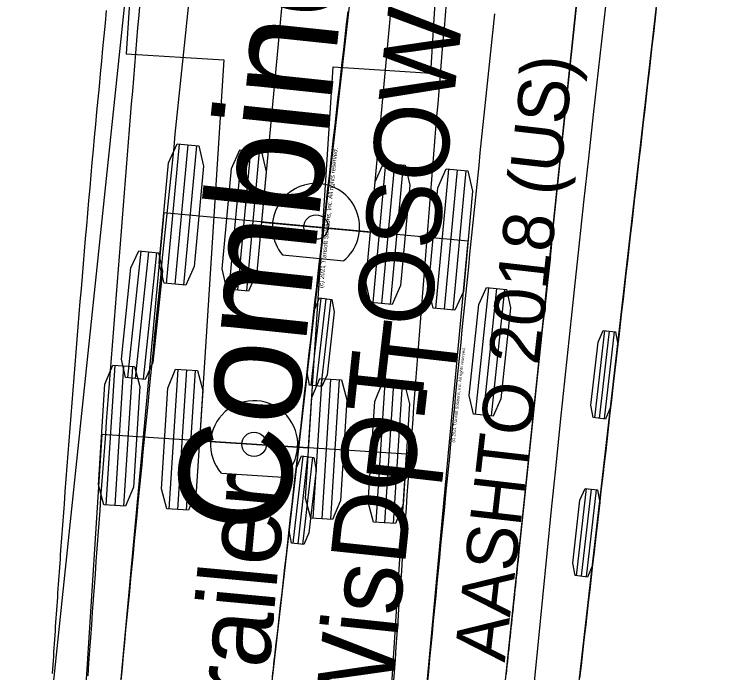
# Model space of a CAD drawing. Extents: x -14 to 1565148, y -25 to 642856.
# Drawn here: x 1564790.38 to 1564808.78, y 636112.11 to 636129.38 of the extents above; entities that cross this region are included whole.
import ezdxf

# ---------------------------------------------------------------- set-up
doc = ezdxf.new("R2010")
doc.units = 0
for name, color, linetype in [('DR_P_Drainage_Area', 7, 'Continuous'), ('GE_P_Alignment', 7, 'Continuous'), ('MT_P_Cells', 7, 'Continuous'), ('PF_P_Grade_Line', 7, 'Continuous'), ('PV_P_Curb', 7, 'Continuous'), ('PV_X_EOP', 7, 'Continuous')]:
    doc.layers.add(name, color=color, linetype=linetype)

msp = doc.modelspace()

# ---------------------------------------------------------------- linework, layer by layer
at = {"layer": 'DR_P_Drainage_Area'}
msp.add_arc((1566787.273, 635986.808), 1980, 175.493678, 179.898828, dxfattribs=at)
at = {"layer": 'GE_P_Alignment'}
msp.add_arc((1565898.839, 636005.315), 1092, 172.336069, 179.46316, dxfattribs=at)
at = {"layer": 'MT_P_Cells'}
for p, q in [((1564793.799, 636135.822), (1564793.32, 636128.337)), ((1564801.304, 636127.827), (1564801.783, 636135.312)), ((1564793.32, 636128.337), (1564795.882, 636128.174)), ((1564795.882, 636128.174), (1564795.244, 636118.194)), ((1564798.104, 636118.011), (1564798.743, 636127.991)), ((1564798.743, 636127.991), (1564801.304, 636127.827)), ((1564793.028, 636120.173), (1564792.794, 636116.514)), ((1564793.256, 636120.158), (1564793.022, 636116.499)), ((1564793.485, 636120.143), (1564793.251, 636116.484)), ((1564794.674, 636120.067), (1564794.44, 636116.408)), ((1564794.903, 636120.053), (1564794.669, 636116.394)), ((1564795.132, 636120.038), (1564794.898, 636116.379)), ((1564798.45, 636119.826), (1564798.216, 636116.167)), ((1564798.679, 636119.811), (1564798.445, 636116.152)), ((1564798.907, 636119.797), (1564798.673, 636116.138)), ((1564800.097, 636119.721), (1564799.863, 636116.061)), ((1564800.325, 636119.706), (1564800.091, 636116.047)), ((1564800.554, 636119.691), (1564800.32, 636116.032)), ((1564792.682, 636118.358), (1564790.385, 636082.431)), ((1564800.666, 636117.847), (1564792.682, 636118.358)), ((1564792.682, 636118.358), (1564792.682, 636118.358)), ((1564795.244, 636118.194), (1564798.104, 636118.011)), ((1564798.368, 636081.921), (1564800.666, 636117.847)), ((1564795.816, 636117.348), (1564797.429, 636117.244))]:
    msp.add_line(p, q, dxfattribs=at)
for points in [[(1564792.325, 636112.039), (1564792.348, 636112.372), (1564792.372, 636112.705), (1564792.396, 636113.038), (1564792.419, 636113.371), (1564792.443, 636113.703), (1564792.467, 636114.036), (1564792.491, 636114.369), (1564792.515, 636114.702), (1564792.54, 636115.035), (1564792.564, 636115.368), (1564792.588, 636115.701), (1564792.613, 636116.034), (1564792.637, 636116.367), (1564792.662, 636116.7), (1564792.686, 636117.033), (1564792.711, 636117.366), (1564792.736, 636117.699), (1564792.761, 636118.032), (1564792.786, 636118.365), (1564792.811, 636118.697), (1564792.836, 636119.03), (1564792.861, 636119.363), (1564792.886, 636119.696), (1564792.912, 636120.029), (1564792.937, 636120.362), (1564792.963, 636120.695), (1564792.989, 636121.028), (1564793.014, 636121.361), (1564793.04, 636121.694), (1564793.066, 636122.027), (1564793.092, 636122.36), (1564793.118, 636122.693), (1564793.144, 636123.026), (1564793.171, 636123.359), (1564793.197, 636123.692), (1564793.223, 636124.025), (1564793.25, 636124.357), (1564793.277, 636124.69), (1564793.303, 636125.023), (1564793.33, 636125.356), (1564793.357, 636125.689), (1564793.384, 636126.022), (1564793.411, 636126.355), (1564793.439, 636126.688), (1564793.466, 636127.021), (1564793.493, 636127.354), (1564793.521, 636127.687), (1564793.549, 636128.02), (1564793.576, 636128.352), (1564793.604, 636128.685), (1564793.632, 636129.018), (1564793.66, 636129.351), (1564793.688, 636129.684)], [(1564800.328, 636111.806), (1564800.352, 636112.137), (1564800.375, 636112.469), (1564800.399, 636112.8), (1564800.423, 636113.131), (1564800.447, 636113.462), (1564800.471, 636113.793), (1564800.495, 636114.125), (1564800.519, 636114.456), (1564800.543, 636114.787), (1564800.567, 636115.118), (1564800.591, 636115.449), (1564800.616, 636115.78), (1564800.64, 636116.111), (1564800.664, 636116.442), (1564800.689, 636116.773), (1564800.714, 636117.104), (1564800.738, 636117.435), (1564800.763, 636117.766), (1564800.788, 636118.097), (1564800.813, 636118.428), (1564800.838, 636118.759), (1564800.863, 636119.09), (1564800.889, 636119.421), (1564800.914, 636119.752), (1564800.939, 636120.083), (1564800.965, 636120.413), (1564800.99, 636120.744), (1564801.016, 636121.075), (1564801.042, 636121.406), (1564801.068, 636121.737), (1564801.094, 636122.068), (1564801.12, 636122.398), (1564801.146, 636122.729), (1564801.172, 636123.06), (1564801.198, 636123.391), (1564801.225, 636123.721), (1564801.251, 636124.052), (1564801.278, 636124.383), (1564801.304, 636124.713), (1564801.331, 636125.044), (1564801.358, 636125.375), (1564801.385, 636125.705), (1564801.412, 636126.036), (1564801.439, 636126.366), (1564801.466, 636126.697), (1564801.494, 636127.028), (1564801.521, 636127.358), (1564801.549, 636127.689), (1564801.576, 636128.019), (1564801.604, 636128.35), (1564801.632, 636128.68), (1564801.66, 636129.011), (1564801.688, 636129.341), (1564801.716, 636129.672)]]:
    msp.add_lwpolyline(points, dxfattribs=at)
for points in [[(1564792.971, 636120.176), (1564793.542, 636120.14), (1564793.681, 636119.617), (1564793.513, 636116.982), (1564793.308, 636116.481), (1564792.737, 636116.517), (1564792.598, 636117.04), (1564792.766, 636119.675)], [(1564794.618, 636120.071), (1564795.189, 636120.035), (1564795.328, 636119.511), (1564795.159, 636116.877), (1564794.955, 636116.375), (1564794.384, 636116.412), (1564794.244, 636116.935), (1564794.413, 636119.57)], [(1564798.393, 636119.83), (1564798.964, 636119.793), (1564799.103, 636119.27), (1564798.935, 636116.635), (1564798.73, 636116.134), (1564798.159, 636116.17), (1564798.02, 636116.694), (1564798.189, 636119.328)], [(1564800.04, 636119.724), (1564800.611, 636119.688), (1564800.75, 636119.165), (1564800.582, 636116.53), (1564800.377, 636116.029), (1564799.806, 636116.065), (1564799.667, 636116.588), (1564799.835, 636119.223)]]:
    msp.add_lwpolyline(points, close=True, dxfattribs=at)
msp.add_circle((1564796.674, 636118.102), 0.32, dxfattribs=at)
msp.add_arc((1564796.674, 636118.102), 1.143, 311.3409, 221.3409, dxfattribs=at)
at = {"layer": 'PF_P_Grade_Line'}
for p, q in [((1564797.793, 636133.884), (1564796.869, 636123.927)), ((1564799.724, 636123.662), (1564800.648, 636133.62)), ((1564794.711, 636125.969), (1564794.372, 636122.318)), ((1564794.939, 636125.948), (1564794.6, 636122.297)), ((1564795.167, 636125.926), (1564794.829, 636122.275)), ((1564796.354, 636125.816), (1564796.015, 636122.165)), ((1564796.582, 636125.795), (1564796.243, 636122.144)), ((1564796.81, 636125.774), (1564796.472, 636122.123)), ((1564800.121, 636125.467), (1564799.782, 636121.816)), ((1564800.349, 636125.445), (1564800.01, 636121.794)), ((1564800.578, 636125.424), (1564800.239, 636121.773)), ((1564801.764, 636125.314), (1564801.425, 636121.663)), ((1564801.992, 636125.293), (1564801.653, 636121.642)), ((1564802.22, 636125.272), (1564801.882, 636121.621)), ((1564794.313, 636124.165), (1564790.986, 636088.319)), ((1564802.279, 636123.425), (1564794.313, 636124.165)), ((1564794.313, 636124.165), (1564794.313, 636124.165)), ((1564796.869, 636123.927), (1564799.724, 636123.662)), ((1564798.952, 636087.579), (1564802.279, 636123.425)), ((1564797.417, 636123.065), (1564799.026, 636122.915))]:
    msp.add_line(p, q, dxfattribs=at)
for points in [[(1564793.191, 636111.914), (1564793.223, 636112.247), (1564793.254, 636112.58), (1564793.286, 636112.912), (1564793.318, 636113.245), (1564793.351, 636113.578), (1564793.383, 636113.911), (1564793.415, 636114.244), (1564793.447, 636114.577), (1564793.479, 636114.909), (1564793.512, 636115.242), (1564793.544, 636115.575), (1564793.576, 636115.908), (1564793.609, 636116.241), (1564793.641, 636116.574), (1564793.674, 636116.906), (1564793.707, 636117.239), (1564793.739, 636117.572), (1564793.772, 636117.905), (1564793.805, 636118.238), (1564793.838, 636118.571), (1564793.871, 636118.904), (1564793.904, 636119.236), (1564793.937, 636119.569), (1564793.97, 636119.902), (1564794.003, 636120.235), (1564794.036, 636120.568), (1564794.069, 636120.901), (1564794.103, 636121.234), (1564794.136, 636121.566), (1564794.169, 636121.899), (1564794.203, 636122.232), (1564794.236, 636122.565), (1564794.27, 636122.898), (1564794.304, 636123.231), (1564794.338, 636123.563), (1564794.371, 636123.896), (1564794.405, 636124.229), (1564794.439, 636124.562), (1564794.473, 636124.895), (1564794.507, 636125.228), (1564794.541, 636125.561), (1564794.576, 636125.893), (1564794.61, 636126.226), (1564794.644, 636126.559), (1564794.679, 636126.892), (1564794.713, 636127.225), (1564794.748, 636127.558), (1564794.782, 636127.89), (1564794.817, 636128.223), (1564794.852, 636128.556), (1564794.887, 636128.889), (1564794.922, 636129.222), (1564794.957, 636129.554)], [(1564801.218, 636111.815), (1564801.25, 636112.147), (1564801.282, 636112.479), (1564801.314, 636112.811), (1564801.346, 636113.142), (1564801.378, 636113.474), (1564801.41, 636113.806), (1564801.442, 636114.137), (1564801.474, 636114.469), (1564801.506, 636114.801), (1564801.539, 636115.132), (1564801.571, 636115.464), (1564801.603, 636115.796), (1564801.636, 636116.127), (1564801.668, 636116.459), (1564801.701, 636116.79), (1564801.734, 636117.122), (1564801.766, 636117.453), (1564801.799, 636117.785), (1564801.832, 636118.116), (1564801.865, 636118.448), (1564801.897, 636118.779), (1564801.93, 636119.111), (1564801.963, 636119.442), (1564801.996, 636119.774), (1564802.03, 636120.105), (1564802.063, 636120.437), (1564802.096, 636120.768), (1564802.129, 636121.099), (1564802.163, 636121.431), (1564802.196, 636121.762), (1564802.23, 636122.094), (1564802.263, 636122.425), (1564802.297, 636122.756), (1564802.33, 636123.088), (1564802.364, 636123.419), (1564802.398, 636123.75), (1564802.432, 636124.081), (1564802.466, 636124.413), (1564802.5, 636124.744), (1564802.534, 636125.075), (1564802.568, 636125.406), (1564802.602, 636125.738), (1564802.636, 636126.069), (1564802.671, 636126.4), (1564802.705, 636126.731), (1564802.74, 636127.062), (1564802.774, 636127.393), (1564802.809, 636127.725), (1564802.843, 636128.056), (1564802.878, 636128.387), (1564802.913, 636128.718), (1564802.948, 636129.049), (1564802.983, 636129.38)]]:
    msp.add_lwpolyline(points, dxfattribs=at)
for points in [[(1564794.655, 636125.974), (1564795.224, 636125.921), (1564795.348, 636125.394), (1564795.104, 636122.765), (1564794.885, 636122.27), (1564794.316, 636122.323), (1564794.191, 636122.85), (1564794.435, 636125.479)], [(1564796.297, 636125.822), (1564796.867, 636125.769), (1564796.991, 636125.242), (1564796.747, 636122.613), (1564796.528, 636122.118), (1564795.959, 636122.171), (1564795.834, 636122.698), (1564796.078, 636125.326)], [(1564800.065, 636125.472), (1564800.634, 636125.419), (1564800.758, 636124.892), (1564800.514, 636122.263), (1564800.295, 636121.768), (1564799.726, 636121.821), (1564799.602, 636122.348), (1564799.846, 636124.977)], [(1564801.708, 636125.319), (1564802.277, 636125.267), (1564802.401, 636124.739), (1564802.157, 636122.111), (1564801.938, 636121.616), (1564801.369, 636121.668), (1564801.244, 636122.195), (1564801.488, 636124.824)]]:
    msp.add_lwpolyline(points, close=True, dxfattribs=at)
msp.add_circle((1564798.296, 636123.795), 0.32, dxfattribs=at)
msp.add_arc((1564798.296, 636123.795), 1.143, 309.6968, 219.6968, dxfattribs=at)
at = {"layer": 'PV_P_Curb'}
for p, q in [((1564794.319, 636139.525), (1564791.306, 636110.883)), ((1564803.021, 636109.65), (1564806.035, 636138.292)), ((1564799.632, 636133.639), (1564796.559, 636106.815)), ((1564804.507, 636105.904), (1564807.58, 636132.729)), ((1564793.703, 636123.166), (1564793.354, 636119.851)), ((1564793.91, 636123.144), (1564793.561, 636119.829)), ((1564794.117, 636123.122), (1564793.768, 636119.807)), ((1564802.819, 636122.207), (1564802.47, 636118.892)), ((1564803.026, 636122.185), (1564802.677, 636118.87)), ((1564803.233, 636122.163), (1564802.885, 636118.848)), ((1564798.422, 636121.934), (1564798.16, 636119.649)), ((1564798.552, 636121.919), (1564798.29, 636119.634)), ((1564798.681, 636121.905), (1564798.419, 636119.62)), ((1564805.853, 636121.083), (1564805.591, 636118.798)), ((1564805.982, 636121.068), (1564805.72, 636118.783)), ((1564806.111, 636121.053), (1564805.85, 636118.768)), ((1564797.948, 636117.795), (1564797.686, 636115.51)), ((1564798.077, 636117.78), (1564797.816, 636115.495)), ((1564798.207, 636117.765), (1564797.945, 636115.48)), ((1564805.379, 636116.943), (1564805.117, 636114.658)), ((1564805.508, 636116.929), (1564805.246, 636114.644)), ((1564805.637, 636116.914), (1564805.375, 636114.629))]:
    msp.add_line(p, q, dxfattribs=at)
for points in [[(1564805.115, 636129.555), (1564805.081, 636129.226), (1564805.046, 636128.895), (1564805.011, 636128.565), (1564804.976, 636128.235), (1564804.942, 636127.904), (1564804.907, 636127.573), (1564804.872, 636127.242), (1564804.837, 636126.911), (1564804.802, 636126.58), (1564804.768, 636126.249), (1564804.733, 636125.918), (1564804.698, 636125.586), (1564804.663, 636125.255), (1564804.628, 636124.923), (1564804.593, 636124.591), (1564804.558, 636124.26), (1564804.523, 636123.928), (1564804.488, 636123.596), (1564804.454, 636123.264), (1564804.419, 636122.932), (1564804.384, 636122.6), (1564804.349, 636122.267), (1564804.314, 636121.935), (1564804.279, 636121.603), (1564804.244, 636121.27), (1564804.209, 636120.938), (1564804.174, 636120.605), (1564804.139, 636120.273), (1564804.104, 636119.94), (1564804.069, 636119.607), (1564804.034, 636119.275), (1564803.999, 636118.942), (1564803.964, 636118.61), (1564803.929, 636118.277), (1564803.894, 636117.945), (1564803.859, 636117.612), (1564803.824, 636117.28), (1564803.789, 636116.948), (1564803.754, 636116.616), (1564803.719, 636116.284), (1564803.684, 636115.952), (1564803.649, 636115.62), (1564803.614, 636115.288), (1564803.603, 636115.177), (1564803.591, 636115.066), (1564803.58, 636114.955), (1564803.568, 636114.845), (1564803.556, 636114.734), (1564803.545, 636114.623), (1564803.533, 636114.513), (1564803.521, 636114.402), (1564803.51, 636114.291), (1564803.498, 636114.181), (1564803.486, 636114.07), (1564803.475, 636113.96), (1564803.463, 636113.849), (1564803.452, 636113.739), (1564803.44, 636113.628), (1564803.428, 636113.518), (1564803.417, 636113.407), (1564803.405, 636113.297), (1564803.393, 636113.186), (1564803.382, 636113.076), (1564803.37, 636112.965), (1564803.359, 636112.855), (1564803.347, 636112.744), (1564803.335, 636112.634), (1564803.324, 636112.523), (1564803.312, 636112.413), (1564803.3, 636112.302), (1564803.289, 636112.192), (1564803.277, 636112.081)], [(1564807.213, 636129.525), (1564807.175, 636129.194), (1564807.137, 636128.863), (1564807.099, 636128.532), (1564807.061, 636128.201), (1564807.023, 636127.87), (1564806.985, 636127.539), (1564806.948, 636127.208), (1564806.91, 636126.876), (1564806.872, 636126.545), (1564806.834, 636126.214), (1564806.796, 636125.883), (1564806.758, 636125.552), (1564806.72, 636125.221), (1564806.682, 636124.89), (1564806.644, 636124.558), (1564806.606, 636124.227), (1564806.568, 636123.896), (1564806.53, 636123.565), (1564806.492, 636123.234), (1564806.454, 636122.903), (1564806.416, 636122.571), (1564806.379, 636122.24), (1564806.341, 636121.909), (1564806.303, 636121.578), (1564806.265, 636121.247), (1564806.227, 636120.916), (1564806.189, 636120.585), (1564806.151, 636120.253), (1564806.113, 636119.922), (1564806.075, 636119.591), (1564806.037, 636119.26), (1564805.999, 636118.929), (1564805.961, 636118.598), (1564805.924, 636118.266), (1564805.886, 636117.935), (1564805.848, 636117.604), (1564805.81, 636117.273), (1564805.772, 636116.942), (1564805.734, 636116.611), (1564805.696, 636116.279), (1564805.658, 636115.948), (1564805.621, 636115.617), (1564805.583, 636115.286), (1564805.545, 636114.955), (1564805.507, 636114.624), (1564805.469, 636114.293), (1564805.431, 636113.961), (1564805.393, 636113.63), (1564805.356, 636113.299), (1564805.318, 636112.968), (1564805.28, 636112.637), (1564805.242, 636112.306), (1564805.204, 636111.975)], [(1564791.394, 636112.102), (1564791.401, 636112.213), (1564791.408, 636112.324), (1564791.416, 636112.435), (1564791.423, 636112.546), (1564791.43, 636112.657), (1564791.438, 636112.768), (1564791.445, 636112.879), (1564791.453, 636112.99), (1564791.46, 636113.101), (1564791.468, 636113.212), (1564791.475, 636113.323), (1564791.483, 636113.434), (1564791.49, 636113.545), (1564791.498, 636113.656), (1564791.505, 636113.767), (1564791.513, 636113.877), (1564791.521, 636113.988), (1564791.528, 636114.099), (1564791.536, 636114.21), (1564791.544, 636114.321), (1564791.552, 636114.432), (1564791.559, 636114.543), (1564791.567, 636114.654), (1564791.575, 636114.765), (1564791.583, 636114.876), (1564791.591, 636114.987), (1564791.599, 636115.097), (1564791.606, 636115.208), (1564791.614, 636115.319), (1564791.622, 636115.43), (1564791.63, 636115.541), (1564791.638, 636115.652), (1564791.646, 636115.763), (1564791.654, 636115.873), (1564791.662, 636115.984), (1564791.67, 636116.095), (1564791.678, 636116.205), (1564791.687, 636116.316), (1564791.695, 636116.426), (1564791.703, 636116.537), (1564791.727, 636116.869), (1564791.752, 636117.201), (1564791.777, 636117.533), (1564791.802, 636117.865), (1564791.828, 636118.197), (1564791.853, 636118.529), (1564791.879, 636118.86), (1564791.905, 636119.192), (1564791.931, 636119.523), (1564791.958, 636119.854), (1564791.984, 636120.186), (1564792.011, 636120.517), (1564792.038, 636120.848), (1564792.065, 636121.179), (1564792.092, 636121.51), (1564792.12, 636121.842), (1564792.148, 636122.173), (1564792.176, 636122.504), (1564792.204, 636122.835), (1564792.232, 636123.166), (1564792.261, 636123.497), (1564792.289, 636123.829), (1564792.318, 636124.16), (1564792.348, 636124.491), (1564792.377, 636124.823), (1564792.407, 636125.155), (1564792.436, 636125.486), (1564792.466, 636125.818), (1564792.497, 636126.15), (1564792.527, 636126.482), (1564792.558, 636126.814), (1564792.589, 636127.146), (1564792.62, 636127.478), (1564792.651, 636127.81), (1564792.682, 636128.142), (1564792.714, 636128.474), (1564792.746, 636128.807), (1564792.778, 636129.139), (1564792.81, 636129.472)], [(1564797.153, 636112.002), (1564797.166, 636112.113), (1564797.179, 636112.223), (1564797.191, 636112.333), (1564797.204, 636112.444), (1564797.217, 636112.554), (1564797.254, 636112.885), (1564797.292, 636113.216), (1564797.33, 636113.547), (1564797.368, 636113.879), (1564797.406, 636114.21), (1564797.444, 636114.541), (1564797.482, 636114.872), (1564797.52, 636115.203), (1564797.557, 636115.534), (1564797.595, 636115.865), (1564797.632, 636116.197), (1564797.67, 636116.528), (1564797.707, 636116.859), (1564797.745, 636117.19), (1564797.783, 636117.521), (1564797.82, 636117.852), (1564797.858, 636118.184), (1564797.895, 636118.515), (1564797.933, 636118.846), (1564797.97, 636119.177), (1564798.008, 636119.508), (1564798.045, 636119.839), (1564798.083, 636120.171), (1564798.12, 636120.502), (1564798.158, 636120.833), (1564798.195, 636121.164), (1564798.233, 636121.495), (1564798.27, 636121.826), (1564798.308, 636122.158), (1564798.345, 636122.489), (1564798.383, 636122.82), (1564798.42, 636123.151), (1564798.458, 636123.482), (1564798.495, 636123.814), (1564798.533, 636124.145), (1564798.57, 636124.476), (1564798.608, 636124.807), (1564798.646, 636125.138), (1564798.683, 636125.469), (1564798.721, 636125.801), (1564798.758, 636126.132), (1564798.796, 636126.463), (1564798.834, 636126.794), (1564798.871, 636127.126), (1564798.909, 636127.457), (1564798.947, 636127.788), (1564798.984, 636128.119), (1564799.022, 636128.45), (1564799.06, 636128.782), (1564799.097, 636129.113), (1564799.135, 636129.444)]]:
    msp.add_lwpolyline(points, dxfattribs=at)
for points in [[(1564793.651, 636123.171), (1564794.168, 636123.117), (1564794.275, 636122.637), (1564794.024, 636120.25), (1564793.82, 636119.802), (1564793.303, 636119.856), (1564793.196, 636120.337), (1564793.447, 636122.724)], [(1564802.768, 636122.212), (1564803.285, 636122.158), (1564803.392, 636121.678), (1564803.141, 636119.291), (1564802.936, 636118.843), (1564802.419, 636118.897), (1564802.312, 636119.378), (1564802.563, 636121.765)], [(1564798.39, 636121.938), (1564798.713, 636121.901), (1564798.774, 636121.57), (1564798.585, 636119.925), (1564798.451, 636119.616), (1564798.128, 636119.653), (1564798.068, 636119.984), (1564798.256, 636121.629)], [(1564805.821, 636121.087), (1564806.144, 636121.05), (1564806.204, 636120.719), (1564806.016, 636119.073), (1564805.882, 636118.765), (1564805.559, 636118.802), (1564805.498, 636119.133), (1564805.687, 636120.778)], [(1564797.916, 636117.798), (1564798.239, 636117.761), (1564798.299, 636117.43), (1564798.111, 636115.785), (1564797.977, 636115.476), (1564797.654, 636115.513), (1564797.593, 636115.844), (1564797.782, 636117.49)], [(1564805.346, 636116.947), (1564805.669, 636116.91), (1564805.73, 636116.579), (1564805.541, 636114.934), (1564805.408, 636114.625), (1564805.085, 636114.662), (1564805.024, 636114.993), (1564805.213, 636116.638)]]:
    msp.add_lwpolyline(points, close=True, dxfattribs=at)
at = {"layer": 'PV_X_EOP'}
msp.add_arc((1565898.839, 636005.315), 1100, 172.336069, 180.049147, dxfattribs=at)

# ---------------------------------------------------------------- texts
at = {"layer": 'PF_P_Grade_Line'}
msp.add_text('Gooseneck Horse Trailer', height=2, rotation=84.6968, dxfattribs=at).set_placement((1564794.779, 636087.632))
at = {"layer": 'PV_P_Curb'}
for s, height, rotation, p in [('WisDOT OSOW 2010 (US)', 1.96333, 83.9946, (1564800.164, 636110.541)), ('Combine', 2.945, 83.9946, (1564797.497, 636115.686)), ('AASHTO 2018 (US)', 1.33333, 83.4648, (1564803.242, 636112.376)), ('(c) 2021 Transoft Solutions, Inc. All rights reserved.', 0.1178, 83.9946, (1564798.478, 636122.194)), ('P-T', 2, 83.4648, (1564801.58, 636116.904)), ('(c) 2021 Transoft Solutions, Inc. All rights reserved.', 0.08, 83.4648, (1564801.924, 636118.147))]:
    msp.add_text(s, height=height, rotation=rotation, dxfattribs=at).set_placement(p)

doc.saveas('drawing.dxf')
